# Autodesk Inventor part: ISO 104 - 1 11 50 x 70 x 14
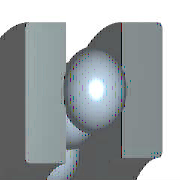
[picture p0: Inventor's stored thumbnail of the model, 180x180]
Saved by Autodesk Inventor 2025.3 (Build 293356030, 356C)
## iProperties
Created: 2024-01
Part Number: ISO 104 - 1 11 50 x 70 x 14
Material: Acciaio, Dolce
Description: Reggispinta Cuscinetto a sfere reggispinta
Document SubType Name: Modeling
Standard: ISO 104
Designer: R5800u
Standards Organization: UNI
Language: it-IT
Size Designation: 1 11 50 x 70 x 14
Categories: <MemberInstance><Categories><Category DisplayName="Parti albero" InternalName="7f7aeb1f-a693-4053-b835-cee3144e0d98" Mnemonic="SHFT"><Category DisplayName="Cusc
Density: 7.85 g/cm^3
Appearance: Semilucidato
IsCustomPart: 0
Author: R5800u
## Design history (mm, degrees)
revolve "Corpo" stored, may be unused: angle "d9" = 90 deg
revolve "Sfera" stored, may be unused: angle "d10" = 90 deg
pattern_circular "Sfere" dims angle "d2" = 360 deg
body "Solid1"
sketch "Schizzo" dims "d3" = 6.16 (= 0.44 x KB)
  geometry: L1 (7, 27.42)-(7, 33.58); L2 (10.08, 30.5)-(3.92, 30.5); L3 (4.2, 31.783)-(4.2, 35); L4 (4.2, 35)-(0, 35); L5 (4.2, 25)-(0, 25); L6 (9.8, 31.783)-(9.8, 35); L7 (9.8, 35)-(14, 35); L8 (14, 35)-(14, 26); L9 (14, 26)-(9.8, 26); L10 (9.8, 26)-(9.8, 29.217); L11 (4.2, 29.217)-(4.2, 25); L12 (-0.8, 0)-(4.8, 0) reference; L13 (0, -0.107)-(0, 2.357) reference; 1 further point
  constraints: 22 end point, 5 perpendicular, 3 parallel, 2 equal length, 2 midpoint, 2 point on line, 1 collinear, 10 other
  dimensions: "d8" = 50 diameter of L5 L12 (= WD); "d11" = 52 diameter of L9 L12 (= KAD1); "d12" = 61 diameter of point (7, 30.5) L12 (= 0.5 x KAD1 + 0.5 x KID1); "d13" = 70 diameter of L4 L12 (= KID1); "d14" = 70 diameter of L7 L12 (= BD); "d15" = 7 distance from line of L13 point (7, 30.5) (= 0.5 x KB); "d16" = 14 distance between parallel lines of L13 L8 (= KB); "d18" = 4.2 distance between parallel lines of L13 L11 (= 0.3 x KB)
fillet "Raccordo1" dims "d4" = 0.6 (= KRS)
fillet "Raccordo2" dims "d5" = 0.6 (= KRS)
other parameters: "WD" = 50 [user parameter; used in 2 equation terms], "KAD1" = 52 [user parameter; used in 3 equation terms], "KID1" = 70 [user parameter; used in 3 equation terms], "BD" = 70 [user parameter; used in 2 equation terms], "KB" = 14 [user parameter; used in 6 equation terms], "KRS" = 0.6 [user parameter; used in 2 equation terms], "d0" = 2.8 (= 0.2 x KB), "d6" = 0, "d7" = 0, "d19" = 0, "d46" = 0, "d47" = 0, "WR" = 25 (= 0.5 x WD) [user parameter], "BC" = 2.55e+07 [user parameter], "BBA" = 90 deg [user parameter], "BC0" = 6.8e+07 [user parameter], "BR" = 35 (= 0.5 x BD) [user parameter]
